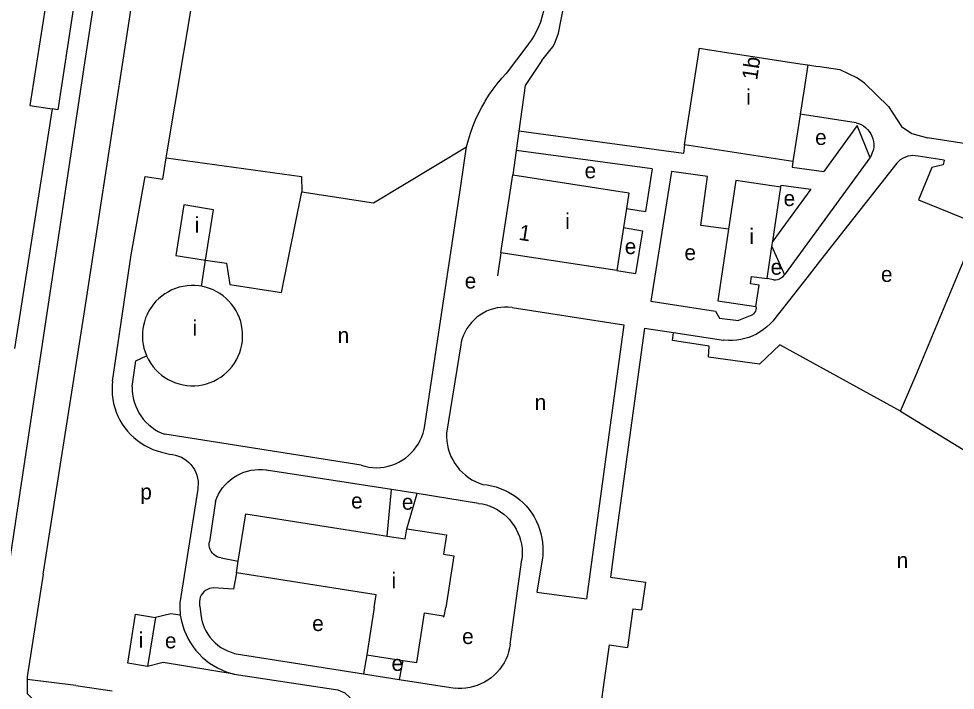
# Model space of a CAD drawing. Extents: x 161093 to 163177, y 379000 to 380904.
# Drawn here: x 161343.5 to 161584.6, y 380478.7 to 380651.6 of the extents above; entities that cross this region are included whole.
import ezdxf

# ---------------------------------------------------------------- set-up
doc = ezdxf.new("R2010")
doc.units = 0
for name, color, linetype in [('BLT_Basislijn', 7, 'Continuous'), ('BLT_Bebouwing', 7, 'Continuous'), ('BLT_Centroide', 7, 'Continuous'), ('BLT_Huisnummer', 7, 'Continuous')]:
    doc.layers.add(name, color=color, linetype=linetype)

msp = doc.modelspace()

# ---------------------------------------------------------------- linework, layer by layer
at = {"layer": 'BLT_Basislijn'}
for p, q in [((161391.8, 380845.99), (161360.68, 380641.96)), ((161474.26, 380644.56), (161468.95, 380637.48)), ((161478.2, 380640.81), (161480.59, 380643.85)), ((161478.2, 380640.81), (161473.83, 380634.43)), ((161546.63, 380639.72), (161548.69, 380639.42)), ((161548.69, 380639.42), (161549.75, 380639.27)), ((161473.83, 380634.43), (161472.23, 380622.62)), ((161559.06, 380624.83), (161544.69, 380627.07)), ((161472.23, 380622.62), (161471.56, 380617.67)), ((161573.4, 380622.04), (161577.46, 380620.91)), ((161610.72, 380615.75), (161577.46, 380620.91)), ((161457.19, 380607.96), (161458.8, 380618.65)), ((161514.91, 380619.15), (161514.67, 380616.88)), ((161471.56, 380617.67), (161470.71, 380611.42)), ((161540.87, 380585.91), (161562.73, 380615.8)), ((161581.77, 380615.18), (161575.04, 380616.22)), ((161506.56, 380612.93), (161504.82, 380601.97)), ((161542.82, 380614.87), (161542.66, 380613.4)), ((161542.66, 380613.4), (161550.74, 380612.29)), ((161569.57, 380614.4), (161549.95, 380589.41)), ((161511.52, 380612.26), (161506.22, 380578.9)), ((161539.7, 380608.19), (161539.81, 380608.74)), ((161539.81, 380608.74), (161547.39, 380607.7)), ((161455.99, 380600.01), (161457.19, 380607.96)), ((161547.39, 380607.7), (161537.63, 380594.35)), ((161499.95, 380602.78), (161504.82, 380601.97)), ((161447.91, 380546.37), (161455.99, 380600.01)), ((161574.73, 380560.34), (161590.62, 380598.62)), ((161499.2, 380597.84), (161504.04, 380597.03)), ((161504.04, 380597.03), (161502.29, 380586.03)), ((161467.62, 380591.36), (161466.76, 380585.4)), ((161537.42, 380592.96), (161540.67, 380585.64)), ((161367.62, 380558.3), (161372.41, 380590.78)), ((161390.53, 380582.7), (161391.59, 380589.42)), ((161549.95, 380589.41), (161546.98, 380585.62)), ((161537.82, 380584.33), (161536.19, 380584.68)), ((161546.98, 380585.62), (161540.13, 380576.89)), ((161540.67, 380585.64), (161540.87, 380585.91)), ((161470.48, 380577.22), (161499.3, 380572.78)), ((161540.13, 380576.89), (161538.76, 380575.18)), ((161531.82, 380575.12), (161528.79, 380573.92)), ((161538.76, 380575.18), (161537.62, 380573.74)), ((161499.3, 380572.78), (161489.62, 380502.19)), ((161504.64, 380571.96), (161496.91, 380515.58)), ((161504.64, 380571.96), (161512.03, 380570.82)), ((161512.03, 380570.82), (161524.92, 380568.84)), ((161457.28, 380567.6), (161453.61, 380544.9)), ((161570.51, 380550.51), (161574.73, 380560.34)), ((161570.51, 380550.51), (161589.77, 380538.79)), ((161431.64, 380536.64), (161381.07, 380544.6)), ((161380.19, 380540), (161382.31, 380539.47)), ((161439.42, 380530.35), (161407.77, 380535.31)), ((161389.56, 380530.45), (161384.94, 380501.21)), ((161438.31, 380518.4), (161439.42, 380530.35)), ((161446.04, 380529.31), (161439.42, 380530.35)), ((161443.39, 380520.28), (161446.04, 380529.31)), ((161461.88, 380526.82), (161446.04, 380529.31)), ((161394.16, 380527.35), (161392.57, 380516.92)), ((161349.74, 380508.54), (161351.72, 380521.12)), ((161496.91, 380515.58), (161495.83, 380507.77)), ((161395.61, 380512.79), (161399.98, 380511.9)), ((161470.02, 380490.55), (161473.02, 380512.32)), ((161478.33, 380512.76), (161476.91, 380503.93)), ((161495.83, 380507.77), (161504.84, 380506.53)), ((161504.84, 380506.53), (161503.86, 380499.36)), ((161476.91, 380503.93), (161489.62, 380502.19)), ((161390.09, 380500.29), (161390.44, 380497.63)), ((161501.62, 380499.67), (161500.25, 380489.7)), ((161501.62, 380499.67), (161503.86, 380499.36)), ((161495.47, 380490.36), (161493.39, 380475.21)), ((161495.47, 380490.36), (161500.25, 380489.7)), ((161399.46, 380488.08), (161432.28, 380482.93)), ((161433.09, 380487.82), (161432.28, 380482.93)), ((161442.39, 380486.36), (161441.46, 380481.49)), ((161398.93, 380482.86), (161425.62, 380478.84)), ((161432.28, 380482.93), (161441.46, 380481.49)), ((161358.16, 380479.89), (161345.65, 380481.46)), ((161441.46, 380481.49), (161455.87, 380479.23)), ((161358.16, 380479.89), (161367.5, 380478.53))]:
    msp.add_line(p, q, dxfattribs=at)
for points in [[(161351.72, 380521.12), (161360.32, 380575.65), (161392.06, 380782.28)], [(161381.41, 380615.77), (161390.63, 380670.67), (161392.83, 380679.02), (161399.83, 380694.41), (161400.14, 380710.8)], [(161351.02, 380674.65), (161360.37, 380673.18), (161353.52, 380628.16), (161352.04, 380628.38)], [(161481.56, 380645.59), (161482.42, 380647.85), (161484.68, 380659.42)], [(161479.03, 380658.36), (161479.02, 380657.07), (161478.93, 380655.78), (161478.77, 380654.5), (161478.52, 380653.23), (161478.2, 380651.98), (161477.79, 380650.75), (161477.32, 380649.55), (161476.77, 380648.38), (161476.15, 380647.25), (161475.46, 380646.16), (161474.7, 380645.11), (161474.26, 380644.56)], [(161480.59, 380643.85), (161481.06, 380644.45), (161481.56, 380645.59)], [(161360.68, 380641.96), (161336.7, 380483.46), (161335.78, 380481.03), (161334.85, 380479.78), (161333.1, 380478.74), (161329.74, 380478.85)], [(161463.45, 380630.15), (161463.58, 380630.39), (161464.55, 380631.93), (161465.59, 380633.43), (161466.69, 380634.87), (161467.85, 380636.27), (161468.95, 380637.48)], [(161549.75, 380639.27), (161554.87, 380638.55), (161559.22, 380636.51)], [(161567.45, 380628.97), (161561.26, 380635.05), (161559.22, 380636.51)], [(161461.12, 380625.6), (161461.85, 380627.19), (161462.68, 380628.81), (161463.45, 380630.15)], [(161567.45, 380628.97), (161570.79, 380623.82), (161573.4, 380622.04)], [(161458.8, 380618.65), (161459.26, 380620.41), (161459.8, 380622.14), (161460.41, 380623.86), (161461.12, 380625.6)], [(161514.67, 380616.88), (161472.23, 380622.62)], [(161562.73, 380615.8), (161559.36, 380624.09), (161550.74, 380612.29)], [(161559.06, 380624.83), (161559.72, 380624.62), (161560.36, 380624.34), (161560.96, 380623.99), (161561.51, 380623.57), (161562.01, 380623.09), (161562.46, 380622.56), (161562.84, 380621.98), (161563.15, 380621.36), (161563.38, 380620.7), (161563.54, 380620.03), (161563.62, 380619.34), (161563.63, 380618.64), (161563.55, 380617.95), (161562.73, 380615.8)], [(161416.36, 380607.02), (161434.85, 380604.23), (161458.8, 380618.65)], [(161372.41, 380590.78), (161375.99, 380611.01), (161380.53, 380610.27), (161381.41, 380615.77)], [(161381.41, 380615.77), (161416.26, 380611.01), (161416.36, 380607.02)], [(161506.56, 380612.93), (161471.56, 380617.67)], [(161575.04, 380616.22), (161574.39, 380616.33), (161573.72, 380616.36), (161573.06, 380616.31), (161572.41, 380616.18), (161571.78, 380615.98), (161571.17, 380615.7), (161570.61, 380615.35), (161570.45, 380615.23)], [(161570.45, 380615.23), (161570.09, 380614.93), (161569.57, 380614.4)], [(161581.77, 380615.18), (161581.54, 380613.95), (161578.61, 380613.33), (161575.12, 380604.97)], [(161526.26, 380597.39), (161519.08, 380598.37), (161520.79, 380611), (161511.52, 380612.26)], [(161391.59, 380589.42), (161397, 380588.63), (161397.82, 380583.18), (161411.15, 380581.14), (161416.36, 380607.02)], [(161575.12, 380604.97), (161588.93, 380599.39)], [(161497.51, 380586.78), (161502.29, 380586.03)], [(161537.82, 380584.33), (161538.36, 380584.37), (161538.89, 380584.48), (161539.39, 380584.67), (161539.87, 380584.93), (161540.3, 380585.26), (161540.67, 380585.64)], [(161470.48, 380577.22), (161469.52, 380577.32), (161468.55, 380577.34), (161467.59, 380577.28), (161466.63, 380577.15), (161465.69, 380576.93), (161464.77, 380576.63), (161463.88, 380576.26), (161463.02, 380575.82), (161462.2, 380575.31), (161461.43, 380574.73), (161460.71, 380574.09), (161460.04, 380573.4), (161459.43, 380572.65), (161458.89, 380571.85), (161458.41, 380571.01), (161458.01, 380570.13), (161457.68, 380569.23), (161457.42, 380568.29), (161457.28, 380567.6)], [(161506.22, 380578.9), (161522.92, 380576.3), (161523.88, 380574.5), (161528.79, 380573.92)], [(161533.27, 380577.48), (161533.31, 380577.08), (161533.27, 380576.68), (161533.15, 380576.3), (161532.96, 380575.94), (161532.7, 380575.63)], [(161532.7, 380575.63), (161532.39, 380575.38), (161532.03, 380575.19), (161531.82, 380575.12)], [(161537.62, 380573.74), (161536.89, 380572.96), (161536.1, 380572.23), (161535.25, 380571.54)], [(161570.51, 380550.51), (161539.43, 380567.62), (161534.21, 380562.67), (161521.11, 380564.44), (161521.29, 380567.25), (161511.81, 380568.73), (161512.03, 380570.82)], [(161535.25, 380571.54), (161534.38, 380570.95), (161533.45, 380570.41), (161532.48, 380569.94), (161531.48, 380569.55), (161530.46, 380569.23), (161529.41, 380568.99), (161528.35, 380568.83), (161527.28, 380568.74), (161526.2, 380568.74), (161525.13, 380568.82), (161524.92, 380568.84)], [(161372.68, 380556.89), (161373.64, 380563.53), (161376.4, 380564.79)], [(161367.62, 380558.3), (161367.52, 380557.14), (161367.49, 380555.99), (161367.55, 380554.83), (161367.69, 380553.68), (161367.9, 380552.55), (161368.2, 380551.43), (161368.57, 380550.33), (161369.01, 380549.27), (161369.53, 380548.23), (161370.12, 380547.24), (161370.77, 380546.28), (161371.49, 380545.38), (161372.28, 380544.52), (161373.11, 380543.73), (161374.01, 380542.99), (161374.95, 380542.31), (161375.93, 380541.71), (161376.95, 380541.17), (161378.01, 380540.7), (161379.1, 380540.31), (161380.19, 380540)], [(161372.68, 380556.89), (161372.7, 380555.89), (161372.78, 380554.89), (161372.95, 380553.89), (161373.2, 380552.92), (161373.52, 380551.97), (161373.92, 380551.04), (161374.39, 380550.15), (161374.93, 380549.31), (161375.54, 380548.5), (161376.2, 380547.75), (161376.93, 380547.05), (161377.71, 380546.42), (161378.53, 380545.84), (161379.4, 380545.34), (161380.31, 380544.9), (161381.07, 380544.6)], [(161431.64, 380536.64), (161432.6, 380536.36), (161433.59, 380536.16), (161434.58, 380536.04), (161435.58, 380536), (161436.58, 380536.04), (161437.57, 380536.16), (161438.55, 380536.36), (161439.51, 380536.64), (161440.45, 380536.99), (161441.35, 380537.41), (161442.22, 380537.91), (161443.05, 380538.47), (161443.83, 380539.1), (161444.55, 380539.79), (161445.22, 380540.54), (161445.83, 380541.33), (161446.37, 380542.17), (161446.84, 380543.05), (161447.24, 380543.97), (161447.57, 380544.92), (161447.82, 380545.89), (161447.91, 380546.37)], [(161453.61, 380544.9), (161453.6, 380543.88), (161453.67, 380542.85), (161453.83, 380541.84), (161454.06, 380540.84), (161454.36, 380539.86), (161454.75, 380538.91), (161455.2, 380537.99), (161455.73, 380537.11), (161456.32, 380536.27), (161456.98, 380535.48), (161457.69, 380534.74), (161458.47, 380534.07), (161459.29, 380533.45), (161460.15, 380532.9), (161461.06, 380532.42), (161462, 380532.01), (161462.94, 380531.69)], [(161382.31, 380539.47), (161383.09, 380539.39), (161383.86, 380539.24), (161384.61, 380539), (161385.34, 380538.69), (161386.02, 380538.31), (161386.67, 380537.86), (161387.26, 380537.35), (161387.81, 380536.78), (161388.29, 380536.16), (161388.7, 380535.49), (161389.05, 380534.78), (161389.32, 380534.04), (161389.51, 380533.28), (161389.63, 380532.5), (161389.67, 380531.72), (161389.62, 380530.93), (161389.56, 380530.45)], [(161394.16, 380527.35), (161394.5, 380528.27), (161394.92, 380529.15), (161395.41, 380530), (161395.97, 380530.8), (161396.59, 380531.55), (161397.27, 380532.25), (161398.01, 380532.9), (161398.79, 380533.48), (161399.62, 380533.99), (161400.49, 380534.44), (161401.4, 380534.81), (161402.33, 380535.11), (161403.28, 380535.33), (161404.25, 380535.47), (161405.22, 380535.53), (161406.2, 380535.51), (161407.17, 380535.42), (161407.77, 380535.31)], [(161462.94, 380531.69), (161464.1, 380531.55), (161465.24, 380531.34), (161466.36, 380531.05), (161467.47, 380530.68), (161468.54, 380530.23), (161469.58, 380529.72), (161470.59, 380529.13), (161471.55, 380528.47), (161472.46, 380527.75), (161473.32, 380526.97), (161474.13, 380526.14), (161474.87, 380525.24), (161475.56, 380524.3), (161476.18, 380523.32), (161476.72, 380522.29), (161477.2, 380521.23), (161477.6, 380520.14), (161477.93, 380519.03), (161478.18, 380517.89), (161478.35, 380516.74), (161478.44, 380515.58), (161478.45, 380514.42), (161478.38, 380513.26), (161478.33, 380512.76)], [(161461.88, 380526.82), (161462.88, 380526.65), (161463.87, 380526.4), (161464.83, 380526.07), (161465.77, 380525.66), (161466.67, 380525.19), (161467.53, 380524.64), (161468.34, 380524.03), (161469.11, 380523.36), (161469.82, 380522.63), (161470.47, 380521.84), (161471.05, 380521.01), (161471.57, 380520.13), (161472.02, 380519.22), (161472.39, 380518.27), (161472.69, 380517.3), (161472.92, 380516.3), (161473.06, 380515.3), (161473.12, 380514.28), (161473.11, 380513.26), (161473.02, 380512.32)], [(161395.61, 380512.79), (161395.09, 380512.89), (161394.59, 380513.07), (161394.12, 380513.32), (161393.7, 380513.64), (161393.33, 380514.01), (161393.02, 380514.44), (161392.78, 380514.91), (161392.61, 380515.42), (161392.52, 380515.94), (161392.51, 380516.47), (161392.57, 380516.92)], [(161349.74, 380508.54), (161345.65, 380482.17), (161345.65, 380481.46)], [(161399.51, 380508.92), (161398.75, 380504.71), (161393.63, 380505.06)], [(161393.63, 380505.06), (161393.08, 380505), (161392.55, 380504.86), (161392.04, 380504.65), (161391.57, 380504.36), (161391.14, 380504.01), (161390.77, 380503.61), (161390.46, 380503.15), (161390.22, 380502.65), (161390.06, 380502.13), (161389.97, 380501.58), (161389.97, 380501.03), (161390.04, 380500.48), (161390.09, 380500.29)], [(161384.94, 380501.21), (161384.93, 380500.01), (161385.05, 380497.99)], [(161385.05, 380497.99), (161382.63, 380498.37), (161378.67, 380497.38)], [(161385.05, 380497.99), (161385.39, 380496.44), (161385.69, 380495.27), (161386.08, 380494.13), (161386.54, 380493.02), (161387.07, 380491.94), (161387.67, 380490.9), (161388.34, 380489.9), (161389.08, 380488.95), (161389.88, 380488.05), (161390.73, 380487.2), (161391.64, 380486.42), (161392.6, 380485.69), (161393.61, 380485.03), (161394.65, 380484.44), (161395.74, 380483.92), (161396.86, 380483.47), (161398, 380483.1), (161398.93, 380482.86)], [(161390.44, 380497.63), (161390.63, 380496.68), (161390.9, 380495.76), (161391.25, 380494.86), (161391.67, 380493.99), (161392.15, 380493.15), (161392.71, 380492.36), (161393.33, 380491.62), (161394.01, 380490.93), (161394.74, 380490.31), (161395.52, 380489.74), (161396.35, 380489.24), (161397.22, 380488.81), (161398.12, 380488.46), (161399.04, 380488.18), (161399.46, 380488.08)], [(161470.02, 380490.55), (161469.85, 380489.55), (161469.6, 380488.56), (161469.28, 380487.59), (161468.89, 380486.65), (161468.42, 380485.75), (161467.88, 380484.88), (161467.27, 380484.06), (161466.61, 380483.29), (161465.88, 380482.57), (161465.1, 380481.91), (161464.27, 380481.32), (161463.4, 380480.79), (161462.49, 380480.33), (161461.54, 380479.95), (161460.57, 380479.64), (161459.58, 380479.41), (161458.57, 380479.25), (161457.56, 380479.18), (161456.54, 380479.18), (161455.87, 380479.23)], [(161398.93, 380482.86), (161380.66, 380485.87), (161376.6, 380484.82)], [(161345.65, 380481.46), (161345.62, 380477.82), (161347.33, 380476.11), (161348.07, 380475.86), (161366.62, 380472.88)], [(161425.62, 380478.84), (161427.47, 380478.02), (161428.69, 380476.79), (161429.42, 380474.99), (161429.5, 380473.03), (161428.85, 380469.26)]]:
    msp.add_lwpolyline(points, dxfattribs=at)
at = {"layer": 'BLT_Bebouwing'}
for p, q in [((161351.94, 380665.09), (161346.3, 380629.28)), ((161517.21, 380634.15), (161518.72, 380644)), ((161518.72, 380644), (161521.35, 380643.59)), ((161521.35, 380643.59), (161521.42, 380643.58)), ((161521.42, 380643.58), (161525.8, 380642.91)), ((161525.8, 380642.91), (161544.65, 380640.02)), ((161544.65, 380640.02), (161544.71, 380640.01)), ((161544.71, 380640.01), (161546.63, 380639.72)), ((161546.63, 380639.72), (161545.6, 380632.97)), ((161514.91, 380619.15), (161517.21, 380634.15)), ((161545.6, 380632.97), (161544.69, 380627.07)), ((161352.04, 380628.38), (161342.38, 380566.68)), ((161346.3, 380629.28), (161352.04, 380628.38)), ((161544.65, 380626.83), (161542.82, 380614.87)), ((161544.69, 380627.07), (161544.65, 380626.83)), ((161542.82, 380614.87), (161514.91, 380619.15)), ((161467.62, 380591.36), (161470.71, 380611.42)), ((161528.13, 380609.92), (161526.26, 380597.39)), ((161539.7, 380608.19), (161528.13, 380609.92)), ((161537.63, 380594.35), (161539.7, 380608.19)), ((161469.77, 380605.05), (161469.78, 380605.14)), ((161499.95, 380602.78), (161499.2, 380597.84)), ((161499.2, 380597.84), (161497.51, 380586.78)), ((161526.26, 380597.39), (161523.5, 380578.94)), ((161537.42, 380592.96), (161537.63, 380594.35)), ((161497.51, 380586.78), (161467.62, 380591.36)), ((161536.19, 380584.68), (161537.42, 380592.96)), ((161383.93, 380590.63), (161391.59, 380589.42)), ((161523.5, 380578.94), (161533.27, 380577.48)), ((161376.37, 380564.85), (161376.4, 380564.79)), ((161436.83, 380518.63), (161438.31, 380518.4)), ((161399.51, 380508.92), (161399.98, 380511.9)), ((161434.98, 380500), (161433.09, 380487.82)), ((161378.67, 380497.38), (161376.6, 380484.82)), ((161433.09, 380487.82), (161442.39, 380486.36))]:
    msp.add_line(p, q, dxfattribs=at)
for points in [[(161470.71, 380611.42), (161500.57, 380606.81), (161499.95, 380602.78)], [(161385.98, 380603.64), (161383.93, 380590.63)], [(161392.19, 380593.21), (161393.65, 380602.43), (161385.98, 380603.64)], [(161391.59, 380589.42), (161392.19, 380593.21)], [(161533.27, 380577.48), (161534.09, 380582.99), (161531.89, 380583.31), (161532.18, 380585.27), (161536.19, 380584.68)], [(161390.53, 380582.7), (161389.85, 380582.81), (161388.84, 380582.9), (161387.82, 380582.91), (161386.81, 380582.84), (161385.8, 380582.69), (161384.81, 380582.46), (161383.84, 380582.16), (161382.9, 380581.77), (161381.99, 380581.32), (161381.12, 380580.8), (161380.3, 380580.2), (161379.52, 380579.55), (161378.79, 380578.84), (161378.13, 380578.07), (161377.52, 380577.25), (161376.99, 380576.39), (161376.52, 380575.48), (161376.13, 380574.55), (161375.81, 380573.58), (161375.56, 380572.6), (161375.43, 380571.81)], [(161392.8, 380582.08), (161391.84, 380582.4), (161390.85, 380582.65), (161390.53, 380582.7)], [(161394.44, 380581.32), (161393.53, 380581.77), (161392.8, 380582.08)], [(161376.97, 380563.66), (161377.5, 380562.79), (161378.1, 380561.97), (161378.77, 380561.2), (161379.49, 380560.49), (161380.26, 380559.83), (161381.09, 380559.23), (161381.96, 380558.71), (161382.87, 380558.25), (161383.81, 380557.87), (161384.77, 380557.56), (161385.76, 380557.33), (161386.77, 380557.17), (161387.78, 380557.1), (161388.8, 380557.1), (161389.81, 380557.19), (161390.81, 380557.36), (161391.8, 380557.6), (161392.76, 380557.92), (161393.7, 380558.31), (161394.6, 380558.78), (161395.46, 380559.32), (161396.28, 380559.92), (161397.05, 380560.59), (161397.76, 380561.31), (161398.42, 380562.09), (161399.01, 380562.92), (161399.53, 380563.79), (161399.99, 380564.7), (161400.37, 380565.64), (161400.67, 380566.61), (161400.9, 380567.6), (161401.05, 380568.6), (161401.12, 380569.62), (161401.11, 380570.63), (161401.02, 380571.64), (161400.85, 380572.65), (161400.61, 380573.63), (161400.28, 380574.6), (161399.89, 380575.53), (161399.42, 380576.43), (161398.88, 380577.29), (161398.27, 380578.11), (161397.6, 380578.87), (161396.87, 380579.58), (161396.09, 380580.24), (161395.27, 380580.82), (161394.44, 380581.32)], [(161375.43, 380571.81), (161375.33, 380570.8), (161375.3, 380569.78), (161375.36, 380568.77), (161375.5, 380567.76), (161375.71, 380566.77), (161376.01, 380565.8), (161376.37, 380564.85)], [(161376.4, 380564.79), (161376.82, 380563.93), (161376.97, 380563.66)], [(161399.98, 380511.9), (161401.9, 380524.12)], [(161401.9, 380524.12), (161436.83, 380518.63)], [(161438.31, 380518.4), (161442.98, 380517.66), (161443.39, 380520.28)], [(161443.39, 380520.28), (161453.58, 380518.68), (161452.81, 380513.76), (161455.5, 380513.34), (161453.4, 380500)], [(161434.98, 380500), (161435.49, 380503.26), (161399.51, 380508.92)], [(161442.39, 380486.36), (161445.95, 380485.8), (161447.96, 380498.6), (161452.77, 380497.84), (161452.74, 380497.61), (161453.05, 380497.73), (161453.4, 380500)], [(161376.6, 380484.82), (161371.55, 380485.67), (161373.52, 380498.24), (161378.67, 380497.38)]]:
    msp.add_lwpolyline(points, dxfattribs=at)

# ---------------------------------------------------------------- texts
at = {"layer": 'BLT_Centroide'}
for s, p in [('i', (161530.77, 380629.44)), ('e', (161548.54, 380619.1)), ('e', (161489.17, 380610.51)), ('e', (161540.42, 380603.37)), ('i', (161484.16, 380597.5)), ('i', (161388.78, 380596.53)), ('i', (161531.59, 380593.56)), ('e', (161499.51, 380590.99)), ('e', (161514.89, 380589.42)), ('e', (161537.08, 380585.68)), ('e', (161565.49, 380583.83)), ('e', (161458.3, 380582.13)), ('i', (161388.22, 380570)), ('n', (161425.59, 380568.09)), ('n', (161476.32, 380550.84)), ('p', (161374.76, 380527.82)), ('e', (161429.05, 380525.5)), ('e', (161442.13, 380525.18)), ('n', (161569.53, 380510.15)), ('i', (161439.44, 380504.97)), ('e', (161419.03, 380493.93)), ('i', (161374.37, 380489.63)), ('e', (161381.11, 380489.48)), ('e', (161457.64, 380490.59)), ('e', (161439.46, 380483.68))]:
    msp.add_text(s, height=4, dxfattribs=at).set_placement(p)
at = {"layer": 'BLT_Huisnummer'}
for s, rotation, p in [('1b', 81.279, (161533.58, 380635.63)), ('1', 351.1675, (161472.04, 380594.71))]:
    msp.add_text(s, height=4, rotation=rotation, dxfattribs=at).set_placement(p)

doc.saveas('drawing.dxf')
